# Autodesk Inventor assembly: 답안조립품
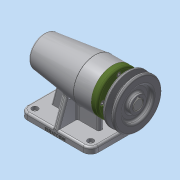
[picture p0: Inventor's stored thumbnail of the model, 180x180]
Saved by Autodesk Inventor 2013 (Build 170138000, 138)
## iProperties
Created: 2018-09
Part Number: 답안조립품
Document SubType Name: Assembly
Designer: Administrator
Author: Administrator
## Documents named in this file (12)
- C:\Users\Administrator\Desktop\480908V1011\답안조립품.iam
- C:\Users\Administrator\Desktop\480908V1011\본체 0.736.ipt
- C:\Users\Administrator\Desktop\480908V1011\멈춤나사 M3.ipt
- C:\Users\Administrator\Desktop\480908V1011\베어링 6004.ipt
- C:\Users\Administrator\Desktop\480908V1011\베어링 51202.ipt
- C:\Users\Administrator\Desktop\480908V1011\볼트 M4.ipt
- C:\Users\Administrator\Desktop\480908V1011\어댑터슬리브.ipt
- C:\Users\Administrator\Desktop\480908V1011\오일 실.ipt
- C:\Users\Administrator\Desktop\480908V1011\축.ipt
- C:\Users\Administrator\Desktop\480908V1011\커버.ipt
- C:\Users\Administrator\Desktop\480908V1011\키 5 x 5 x 16.ipt
- C:\Users\Administrator\Desktop\480908V1011\V벨트풀리.ipt
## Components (1 placed, 1 different names)
1. V벨트풀리:1
